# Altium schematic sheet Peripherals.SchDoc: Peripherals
size A4; Project: STM32MP15-DISCO PI; Date: Not used; ApprovedBy: Not used; CheckedBy: Not used; Author: Not used; CompanyName: STMicroelectronics; DrawnBy: Not used; Engineer: Not used; Organization: Not used; Address1: Not used; Address2: Not used; Address3: Not used; Address4: Not used; DocumentNumber: 15; Revision: Not used; SheetNumber: 15; SheetTotal: 17
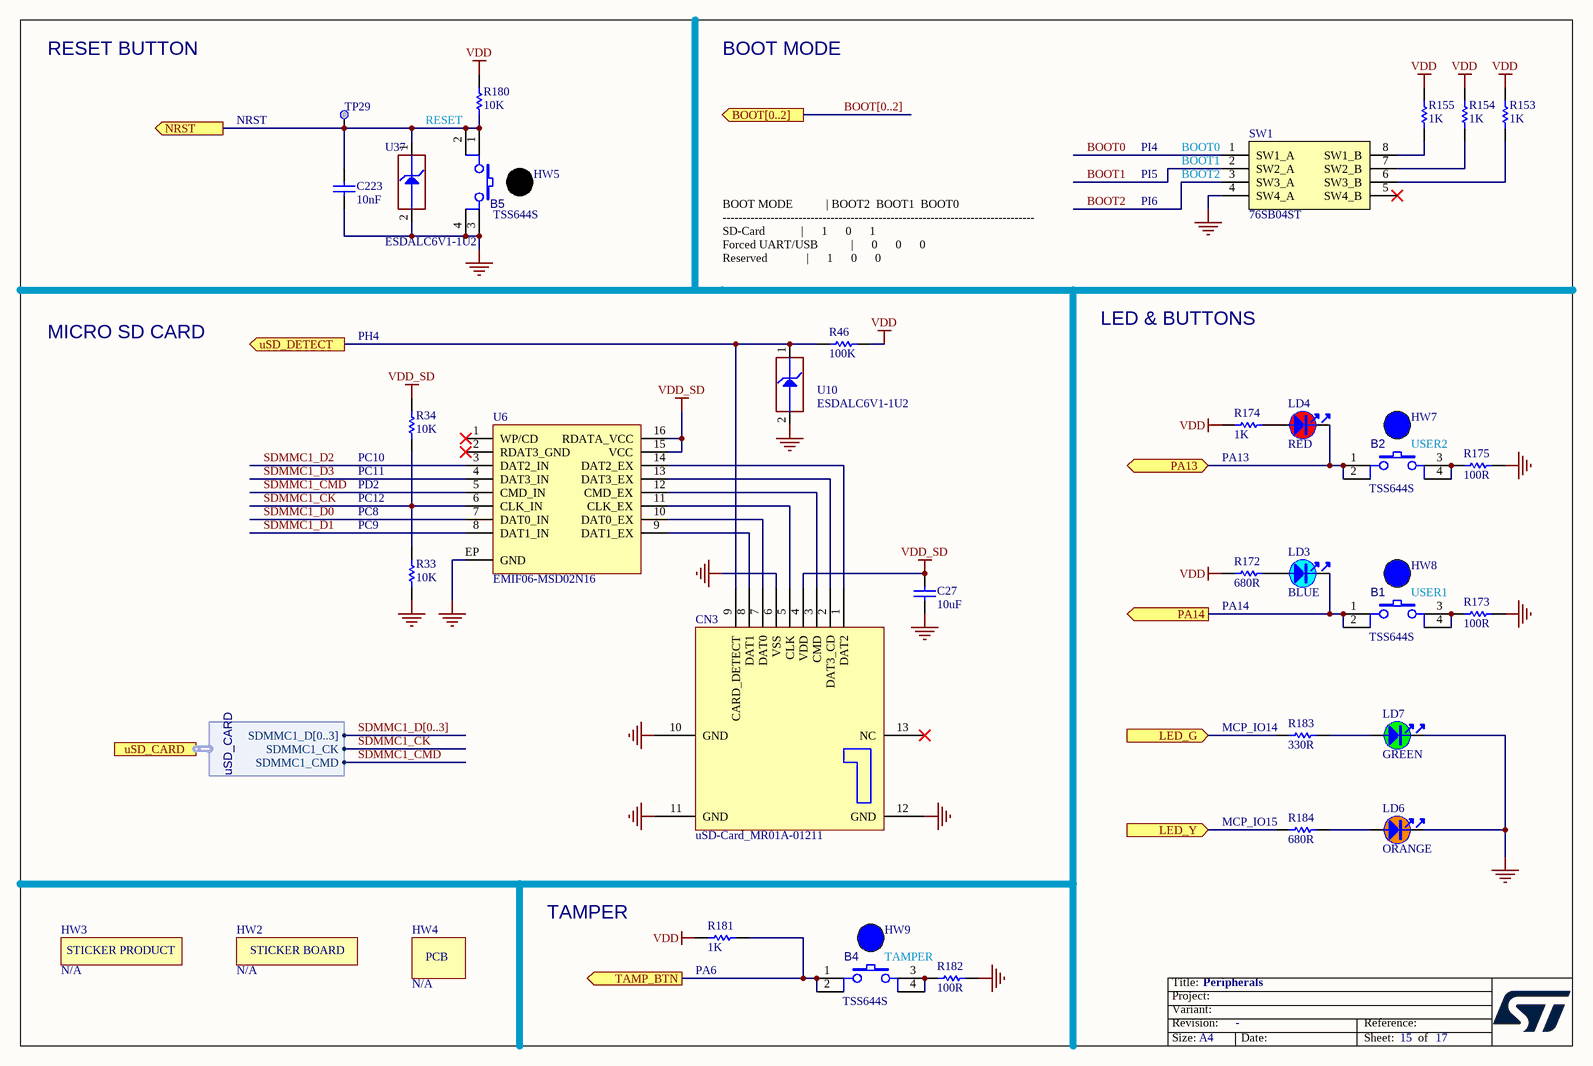
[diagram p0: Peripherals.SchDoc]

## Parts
B1  value TSS644S  [SWI_KNITTER_TSS644S]  (hidden comment: SW_PUSH_SMD)
B2  value TSS644S  [SWI_KNITTER_TSS644S]  (hidden comment: SW_PUSH_SMD)
B4  value TSS644S  [SWI_KNITTER_TSS644S]  (hidden comment: SW_PUSH_SMD)
B5  value TSS644S  [SWI_KNITTER_TSS644S]  (hidden comment: SW_PUSH_SMD)
C27  value 10uF  [C0603]  (hidden comment: Capacitor)
C223  value 10nF  [C0402]  (hidden comment: Capacitor)
CN3  value uSD-Card_MR01A-01211  [CON_MICROSD_ATOM_MR01A-01211]  (hidden comment: MR01A-01211)
HW2  STICKER_BOARD  [STICKER_BOARD_25X9]  (value not drawn)  (no BOM)
HW3  STICKER_PRODUCT  [STICKER_PRODUCT_25X9]  (value not drawn)  (no BOM)
HW4  PCB  (value not drawn)  (mechanical)
HW5  SW-CAP-KTSC-62K  (value not drawn)  (mechanical)
HW7  AKTSC62B  (value not drawn)  (mechanical)
HW8  AKTSC62B  (value not drawn)  (mechanical)
HW9  AKTSC62B  (value not drawn)  (mechanical)
LD3  value BLUE  [LED_0603_SMD-B_BLUE_H0P4]  (hidden comment: LED_blue)
LD4  value RED  [LED_0603_RED]  (hidden comment: LED_red)
LD6  value ORANGE  [LED_0603_ORANGE_H0P4]  (hidden comment: LED_orange)
LD7  value GREEN  [LED_0603_GREEN]  (hidden comment: LED_green)
R33  value 10K  [R0402]  (hidden comment: Resistor)
R34  value 10K  [R0402]  (hidden comment: Resistor)
R46  value 100K  [R0402]  (hidden comment: Resistor)
R153  value 1K  [R0402]  (hidden comment: Resistor)
R154  value 1K  [R0402]  (hidden comment: Resistor)
R155  value 1K  [R0402]  (hidden comment: Resistor)
R172  value 680R  [R0402]  (hidden comment: Resistor)
R173  value 100R  [R0402]  (hidden comment: Resistor)
R174  value 1K  [R0402]  (hidden comment: Resistor)
R175  value 100R  [R0402]  (hidden comment: Resistor)
R180  value 10K  [R0402]  (hidden comment: Resistor)
R181  value 1K  [R0402]  (hidden comment: Resistor)
R182  value 100R  [R0402]  (hidden comment: Resistor)
R183  value 330R  [R0402]  (hidden comment: Resistor)
R184  value 680R  [R0402]  (hidden comment: Resistor)
SW1  76SB04ST  [SWI_GRAYHILL-INC_76SB04ST]
TP29  Test Point  [TP_SMD_1MM]  (value not drawn)  (no BOM)
U6  EMIF06-MSD02N16  [ESD_UQFN16L-EPAD_3P5X1P2_P040]
U10  value ESDALC6V1-1U2  [ESD_ST0201]  (hidden comment: ESD-TRANSIL)
U37  value ESDALC6V1-1U2  [ESD_ST0201]  (hidden comment: ESD-TRANSIL)

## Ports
BOOT[0..2] (out), LED_G (in), LED_Y (in), NRST (out), PA13 (bidir), PA14 (out), TAMP_BTN (out), uSD_CARD (harness uSD_CARD), uSD_DETECT (out)

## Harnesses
uSD_CARD: SDMMC1_D[0..3], SDMMC1_CK, SDMMC1_CMD

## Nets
GND: B5.3 B5.4 C27.1 C223.1 CN3.6(VSS) CN3.10(GND) CN3.11(GND) CN3.12(GND) LD6.2 LD7.2 R33.1 R173.2 R175.2 R182.2 SW1.4(SW4_A) U6.EP(GND) U10.2(GND) U37.2(GND)
VDD: R46.1 R153.2 R154.2 R155.2 R172.2 R174.2 R180.2 R181.2
VDD_SD: C27.2 CN3.4(VDD) R34.2 U6.15(VCC) U6.16(RDATA_VCC)
BOOT0: SW1.1(SW1_A)
BOOT1: SW1.2(SW2_A)
BOOT2: SW1.3(SW3_A)
LED_G: R183.1 ; port LED_G
LED_Y: R184.1 ; port LED_Y
NRST: B5.1 B5.2 C223.2 R180.1 TP29.1 U37.1(IO1) ; port NRST
PA13: B2.1 B2.2 LD4.2 ; port PA13
PA14: B1.1 B1.2 LD3.2 ; port PA14
SDMMC1_CK: R33.2 R34.1 U6.6(CLK_IN) ; port uSD_CARD.SDMMC1_CK
SDMMC1_CMD: U6.5(CMD_IN) ; port uSD_CARD.SDMMC1_CMD
SDMMC1_D0: U6.7(DAT0_IN)
SDMMC1_D1: U6.8(DAT1_IN)
SDMMC1_D2: U6.3(DAT2_IN)
SDMMC1_D3: U6.4(DAT3_IN)
TAMP_BTN: B4.1 B4.2 R181.1 ; port TAMP_BTN
uSD_DETECT: CN3.9(CARD_DETECT) R46.2 U10.1(IO1) ; port uSD_DETECT
NetB1_3: B1.3 B1.4 R173.1
NetB2_3: B2.3 B2.4 R175.1
NetB4_3: B4.3 B4.4 R182.1
NetCN3_1: CN3.1(DAT2) U6.14(DAT2_EX)
NetCN3_2: CN3.2(DAT3_CD) U6.13(DAT3_EX)
NetCN3_3: CN3.3(CMD) U6.12(CMD_EX)
NetCN3_5: CN3.5(CLK) U6.11(CLK_EX)
NetCN3_7: CN3.7(DAT0) U6.10(DAT0_EX)
NetCN3_8: CN3.8(DAT1) U6.9(DAT1_EX)
NetLD3_1: LD3.1 R172.1
NetLD4_1: LD4.1 R174.1
NetLD6_1: LD6.1 R184.2
NetLD7_1: LD7.1 R183.2
NetR153_1: R153.1 SW1.6(SW3_B)
NetR154_1: R154.1 SW1.7(SW2_B)
NetR155_1: R155.1 SW1.8(SW1_B)

Not connected (* = marked no-connect by the designer): CN3 13(NC)*; SW1 5(SW4_B)*; U6 1(WP/CD)* 2(RDAT3_GND)*

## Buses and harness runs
bus BOOT[0..2] = port BOOT[0..2]
bus SDMMC1_D[0..3]

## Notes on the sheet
- RESET BUTTON
- BOOT MODE
- NRST
- RESET
- PI4
- PI5
- (near SW1) BOOT0
- (near SW1) BOOT1
- (near SW1) BOOT2
- BOOT MODE	          |	BOOT2 	BOOT1 	BOOT0
  ------------------------------------------------------------------------------
  SD-Card		          |	     1	     0	     1
  Forced UART/USB	          |	     0	     0	     0
  Reserved 		          |	     1	     0	     0
- PI6
- LED & BUTTONS
- MICRO SD CARD
- PH4
- (near R34) PC10
- (near R174) PA13
- (near B2) USER2
- (near R34) PC11
- PD2
- PC12
- PC8
- (near R33) PC9
- (near B1) USER1
- (near R172) PA14
- (near R183) MCP_IO14
- (near R184) MCP_IO15
- TAMPER
- (near R181) PA6

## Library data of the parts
B1 B2 B4 = MCD-02417: Push Button, NO, 0.05A, 12V, 2.6N, SMD, 9.0x6.2mm, T=7.3mm, changeable caps KTSC-6xx; Part_Type: Misc; Manufacturer: KNITTER-SWITCH; Part_Preference: Recommended; Manufacturer_HQ_COO: Unknown; Component_Country_Of_Origin: China; ShowFields: YES; ID: 4523
B5 = MCD-02417: Push Button, NO, 0.05A, 12V, 2.6N, SMD, 9.0x6.2mm, T=7.3mm, changeable caps KTSC-6xx; Manufacturer: KNITTER-SWITCH; Part_Type: Misc; Part_Preference: Recommended; Manufacturer_HQ_COO: Unknown; Component_Country_Of_Origin: China; ShowFields: YES; ID: 4523
C27 = MCD-00099: Capacitor, MLCC, 10uF, 10V, X5R, +/-10%, 0603, T=0.8mm; Manufacturer_Part_Number: GRM188R61A106KE69; Manufacturer: MURATA; Part_Preference: Recommended; Partial_Alternate_Internal_Part_Number: MCD-03152; Order_Code_RS: 2494233; Component_Country_Of_Origin: Japan°°; ShowFields: YES; ID: 2770
C223 = MCD-02198: Capacitor, MLCC, 10nF, 50V, X7R, +/-10%, 0402, T=0.5mm; Manufacturer_Part_Number: CC0402KRX7R9BB103; Manufacturer: YAGEO; Part_Preference: Recommended; Order_Code_RS: 6169644; Component_Country_Of_Origin: China; ShowFields: YES; ID: 4298
CN3 = MCD-00653: Connector_uSD Card, Top Mnt Push-Push; Manufacturer: ATOM; Part_Preference: Recommended; Component_Country_Of_Origin: Unknown; ShowFields: YES; ID: 3087
HW2 = MCD-00235: Sticker Board 25x9 mm; Part_Type: Misc; Part_Preference: Recommended; ShowFields: YES; ID: 2632; Component_Country_Of_Origin: Unknown
HW3 = MCD-00547: Sticker product 25x9 mm; Part_Type: Misc; Part_Preference: Recommended; ShowFields: YES; ID: 3197; Component_Country_Of_Origin: Unknown
HW4 = MCD-00216: PCB, xxxx for PCB number, Y for PCB revision; Part_Type: Misc; Part_Preference: Forbidden; ShowFields: YES; ID: 2653; Component_Country_Of_Origin: Unknown
HW5 = MCD-02420: Black round cap for TSS6x series; Part_Type: Mechanical; Part_Preference: Recommended; Manufacturer: KNITTER-SWITCH; Manufacturer_HQ_COO: Unknown; Partial_Alternate_Internal_Part_Number: MCD-02526; Component_Country_Of_Origin: China; ShowFields: YES; ID: 4526; Alternate_EMS: M
HW7-HW9 = MCD-02136: Switch hat, blue, For KTSC-62B; Part_Type: Mechanical; Part_Preference: Recommended; Manufacturer: APEM; Partial_Alternate_Internal_Part_Number: MCD-02419; Order_Code_RS: 378-6779; Component_Country_Of_Origin: Unknown; ShowFields: YES; ID: 4236
LD3 = MCD-01131: LED Blue, 0603 SMD, Forward Voltage Min=2,8V, Max=3,1V; Part_Type: Display; Manufacturer_Part_Number: 19-217/BHC-ZL1M2RY/3T; Manufacturer: EVERLIGHT; Part_Preference: Forbidden; Full_Alternate_Internal_Part_Number: MCD-02786; Component_Country_Of_Origin: China; ShowFields: YES; ID: 3365
LD4 = MCD-00049: LED, Red, 0603; Manufacturer_Part_Number: 19-213/R6C-AP1Q2B/3T; Manufacturer: EVERLIGHT; Part_Type: Display; Part_Preference: Forbidden; Full_Alternate_Internal_Part_Number: MCD-02899; Component_Country_Of_Origin: China; ShowFields: YES; ID: 2543
LD6 = MCD-00321: LED, Orange, 0603; Part_Type: Display; Manufacturer_Part_Number: 19-217/S2C-AM2N2VY/3T; Manufacturer: EVERLIGHT; Part_Preference: Forbidden; Full_Alternate_Internal_Part_Number: MCD-02785; Component_Country_Of_Origin: China; ShowFields: YES; ID: 2957
LD7 = MCD-00050: LED, Green, 0603; Manufacturer_Part_Number: 19-213SYGC/S530-E2/TR8; Manufacturer: EVERLIGHT; Part_Type: Display; Part_Preference: Forbidden; Partial_Alternate_Internal_Part_Number: MCD-02900; Component_Country_Of_Origin: China; ShowFields: YES; ID: 2542
R33 R34 R180 = MCD-00053: Resistor, 10K, 0402, +/-1%, 1/16W; Manufacturer_Part_Number: RC0402FR-0710KL; Manufacturer: YAGEO; BMS_Part_Number: 9131590; Part_Preference: Recommended; Order_Code_RS: 9239359; Component_Country_Of_Origin: China; ShowFields: YES; ID: 2539
R46 = MCD-00059: Resistor, 100K, 0402, +/-1%, 1/16W; Part_Preference: Recommended; Manufacturer: YAGEO; Manufacturer_Part_Number: RC0402FR-07100KL; Partial_Alternate_Internal_Part_Number: MCD-03301; Order_Code_RS: 2421891; Component_Country_Of_Origin: China; ShowFields: YES; ID: 2533
R153-R155 R174 R181 = MCD-00061: Resistor, 1K, 0402, +/-1%,1/16W; Manufacturer_Part_Number: RC0402FR-071KL; Manufacturer: YAGEO; Part_Preference: Recommended; Order_Code_RS: 9239235; Component_Country_Of_Origin: China; ShowFields: YES; ID: 2532
R172 R184 = MCD-00507: Resistor, 680R, 0402, +/-1%, 1/16W; Manufacturer_Part_Number: RC0402FR-07680RL; Manufacturer: YAGEO; Part_Preference: Recommended; Component_Country_Of_Origin: China; ShowFields: YES; ID: 3238
R173 R175 R182 = MCD-00067: Resistor, 100R, 0402, +/- 1%, 1/16W; Manufacturer_Part_Number: RC0402FR-07100RL; Manufacturer: YAGEO; Part_Preference: Recommended; Order_Code_RS: 9239111; Component_Country_Of_Origin: China; ShowFields: YES; ID: 2527
R183 = MCD-00062: Resistor, 330R, 0402, +/-1%, 1/16W; Manufacturer_Part_Number: RC0402FR-07330RL; Manufacturer: YAGEO; Part_Preference: Recommended; Order_Code_RS: 9239170; Component_Country_Of_Origin: China; ShowFields: YES; ID: 2529
SW1 = MCD-02256: Quad SPST switch, TH, 2.54mm pitch, height 7.5mm; Part_Preference: Recommended; Part_Type: Misc; Manufacturer: ECE; Order_Code_RS: 878-0230; Component_Country_Of_Origin: China°°; ShowFields: YES; ID: 4356
TP29 = MCD-00074: Test Point 1mm; Part_Type: Misc; Part_Preference: Recommended; ShowFields: YES; ID: 2518; Component_Country_Of_Origin: Unknown
U6 = MCD-00249: ESD protection for SD card 2.0; BMS_Part_Number: 9179003; Part_Preference: Recommended; Part_Type: Diode; Manufacturer: STMICROELECTRONICS; Manufacturer_HQ_COO: EU; Order_Code_RS: 917-2716; Component_Country_Of_Origin: Thailand; ShowFields: YES; ID: 2617
U10 U37 = MCD-00170: ESD protection 6V1; Part_Type: Diode; Manufacturer: STMICROELECTRONICS; BMS_Part_Number: 9151132; Part_Preference: Recommended; Manufacturer_HQ_COO: EU; Component_Country_Of_Origin: China; ShowFields: YES; ID: 2696; Order_Code_RS: 795-8404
